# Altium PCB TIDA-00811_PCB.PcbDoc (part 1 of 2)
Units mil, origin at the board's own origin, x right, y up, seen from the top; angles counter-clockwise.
Board outline 2165.35 x 1968.5 mil, 2 copper layers (Top Layer, Bottom Layer), stack 62 mil thick; 184 components, 89 nets, 461 pads, 152 vias.
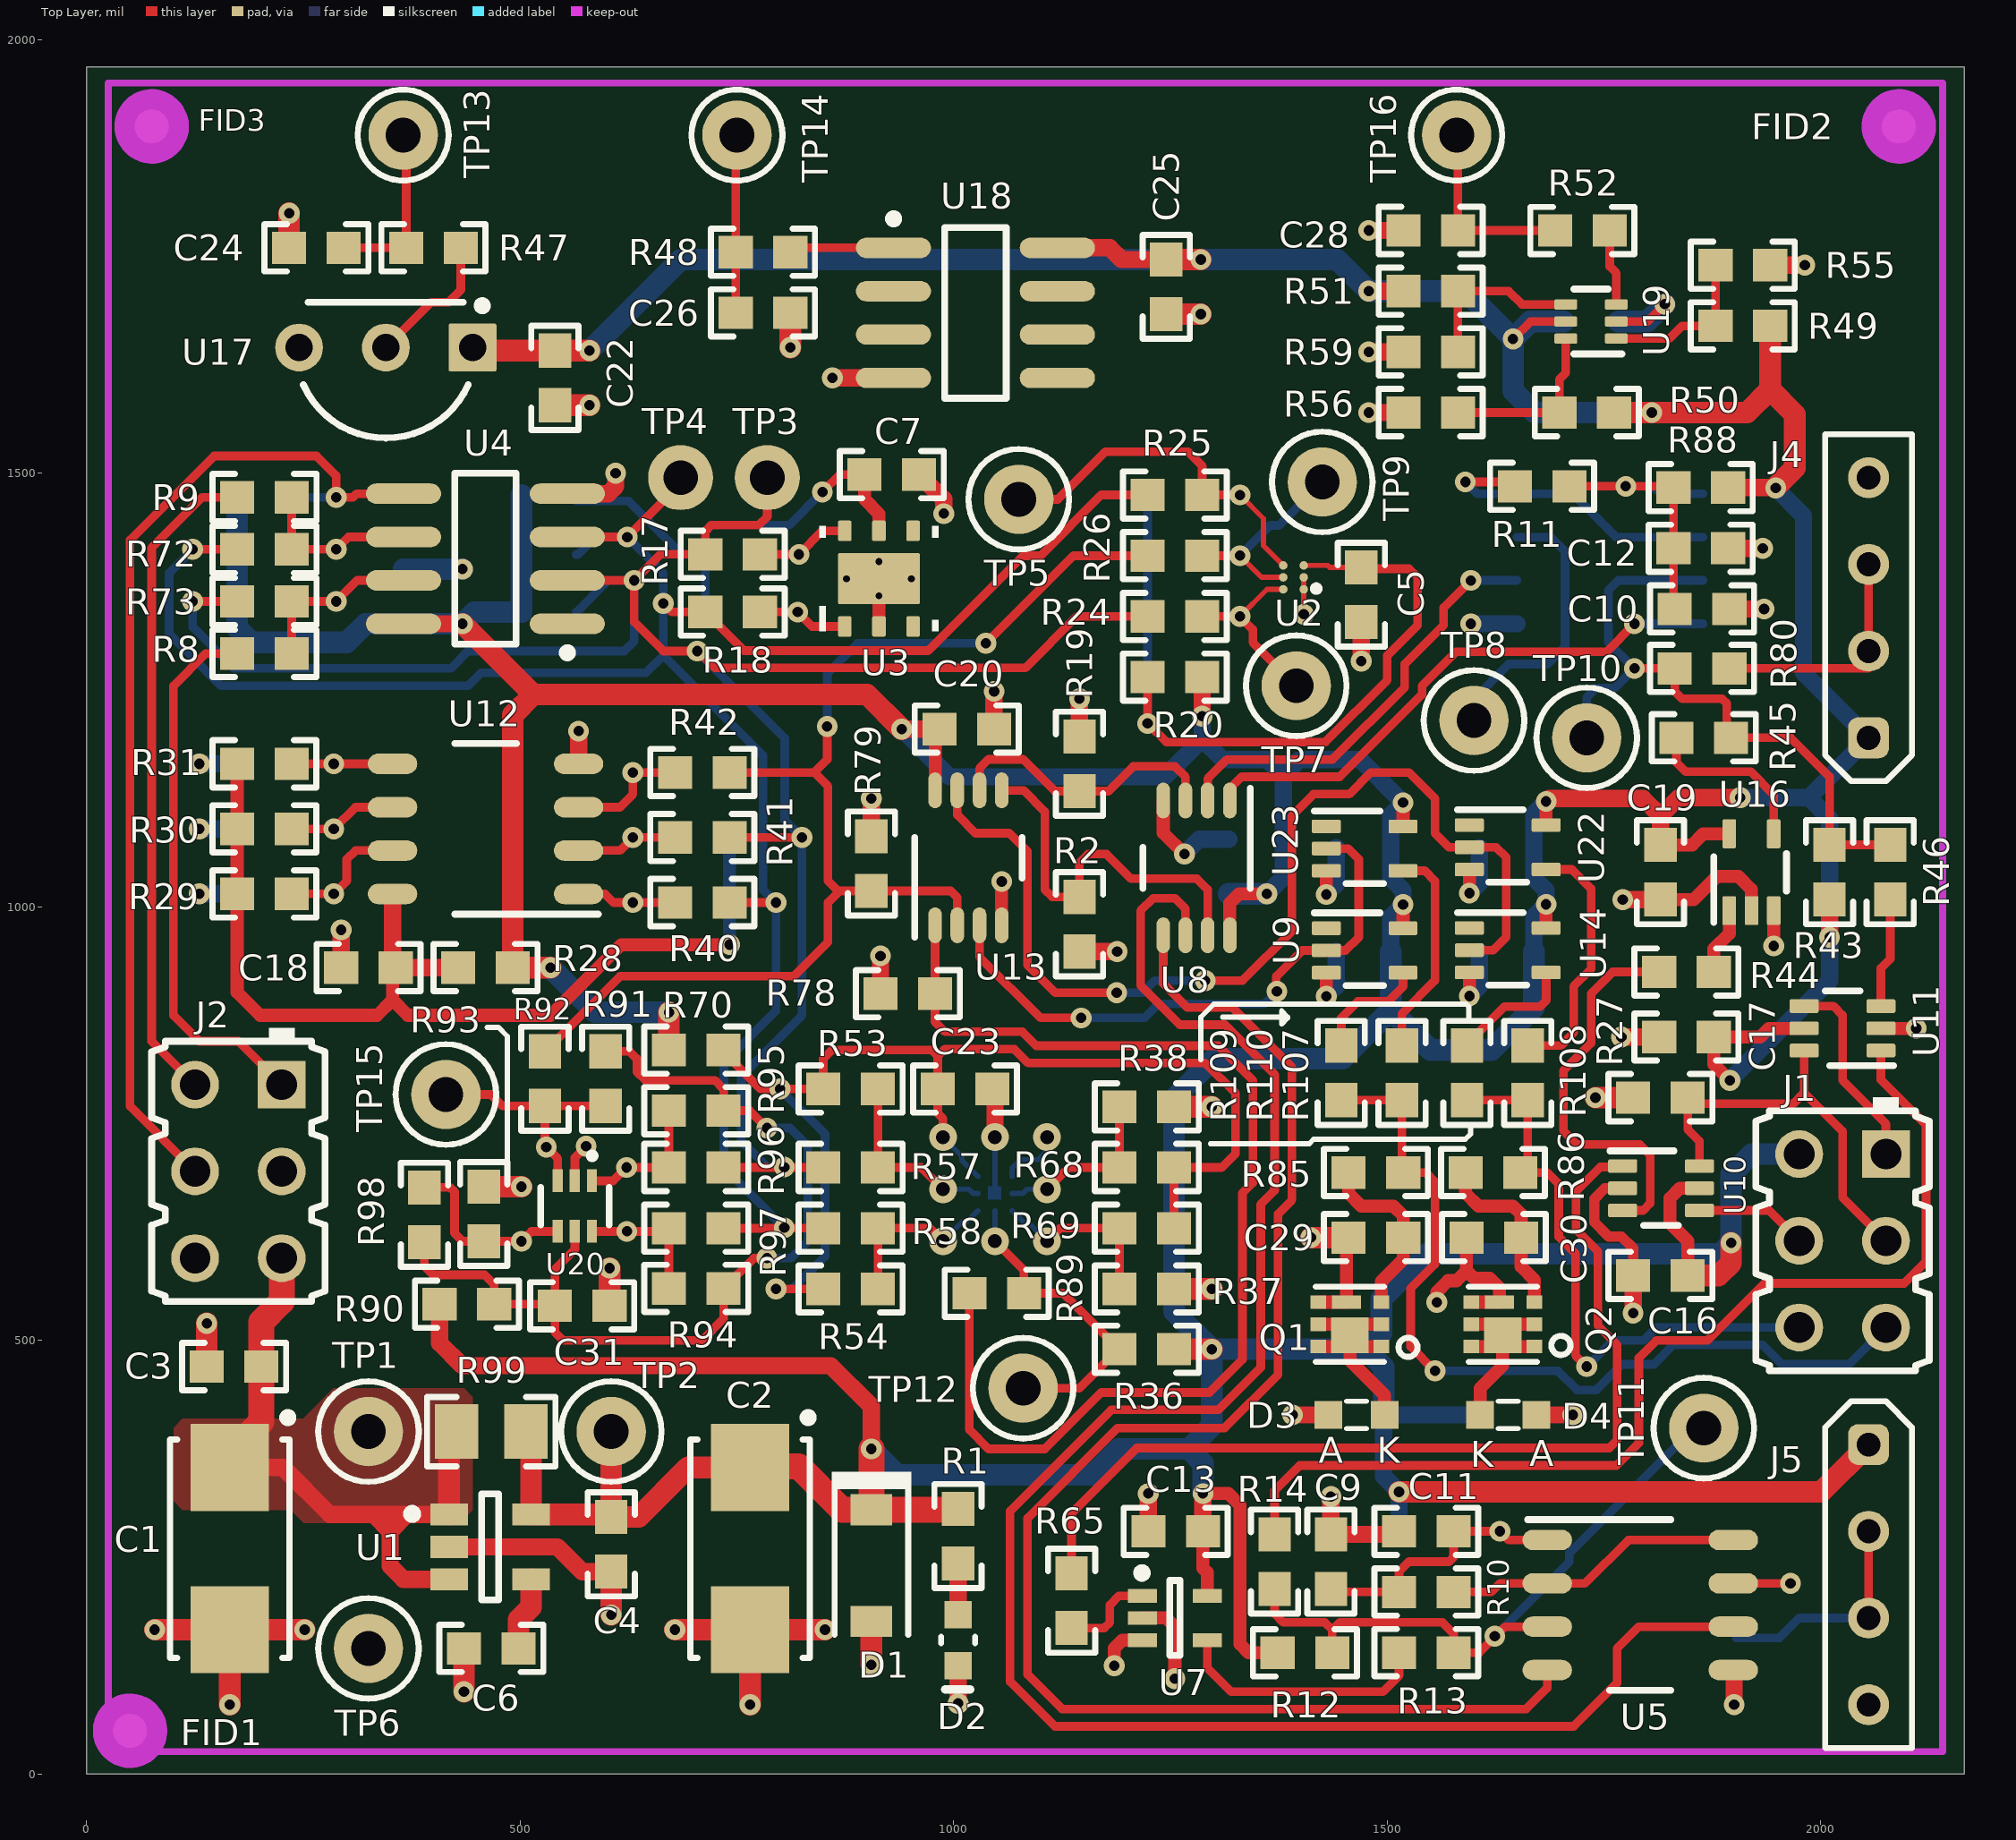
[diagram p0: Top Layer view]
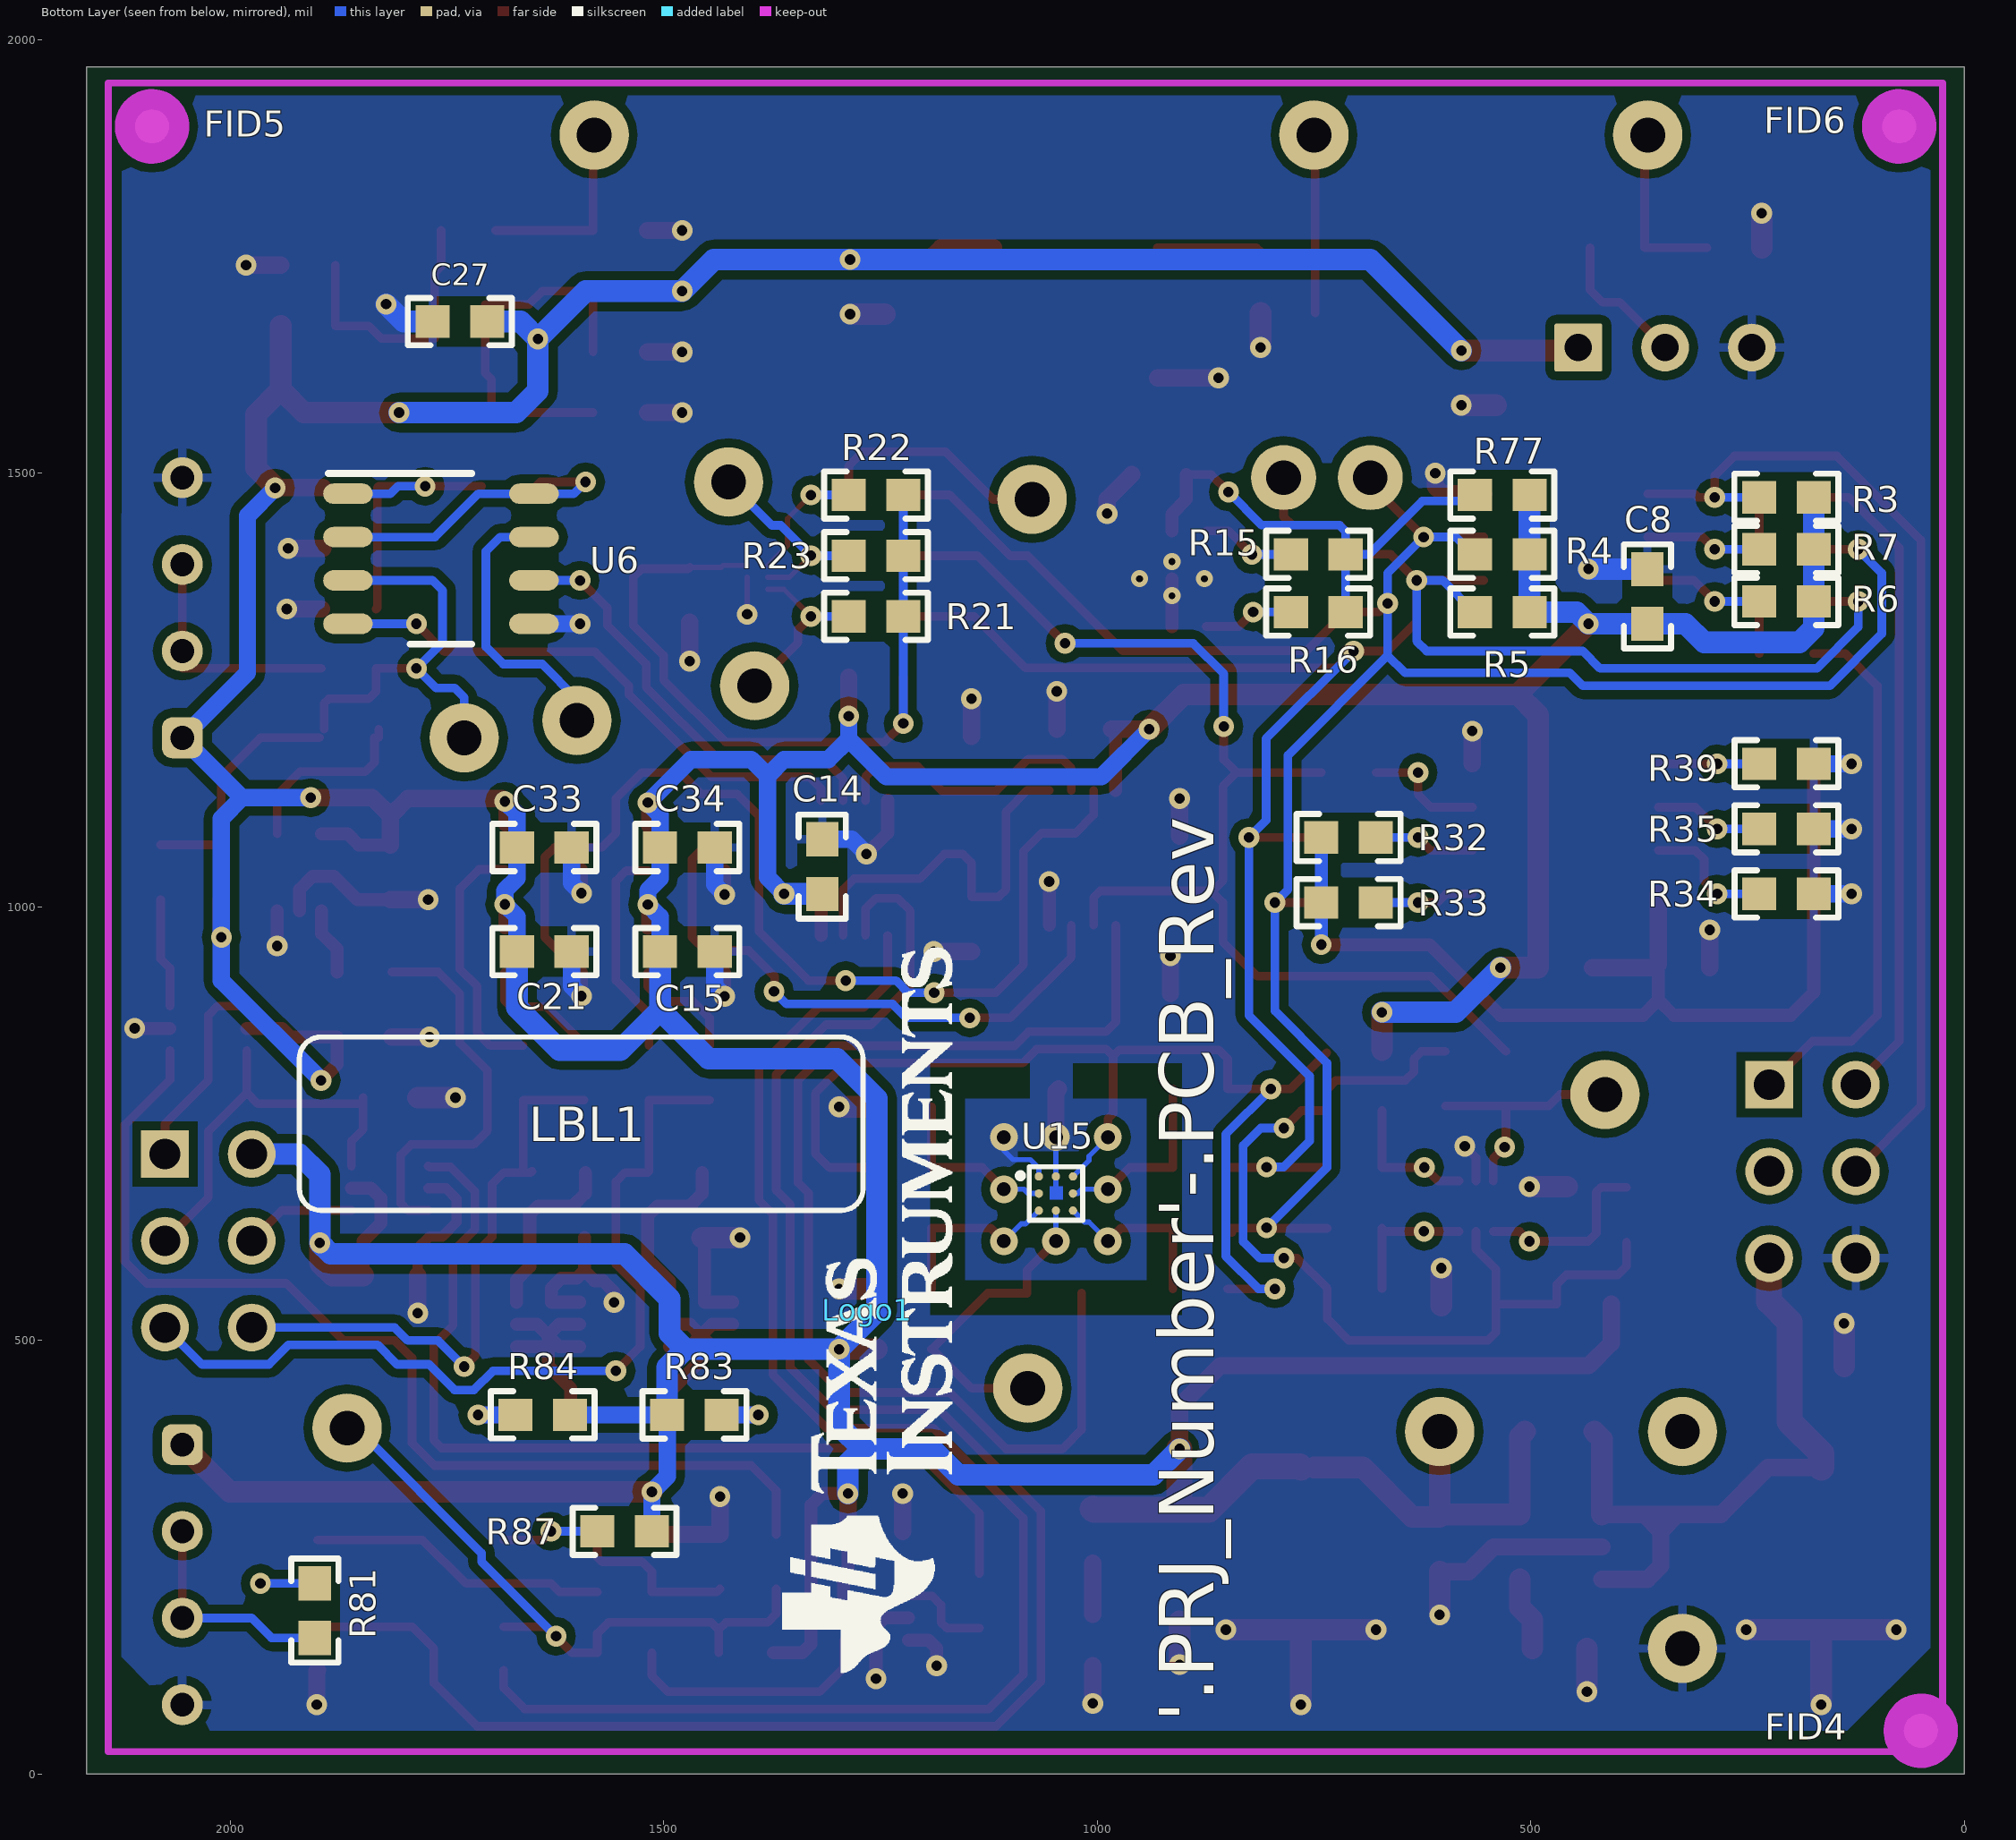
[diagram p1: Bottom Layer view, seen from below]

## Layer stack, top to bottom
Top Solder: solder mask 0.4, Solder Resist, Dk 3.5
Top Layer: signal copper 1.4
Dielectric1: core 59.2, FR-4 High Tg, Dk 4.8
Bottom Layer: signal copper 1.4
Bottom Solder: solder mask 0.4, Solder Resist, Dk 3.5

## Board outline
0,0 0,1968.5 2165.35,1968.5 2165.35,0

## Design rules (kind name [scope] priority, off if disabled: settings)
AcuteAngle [All] p1: minimum=4.50000000000000E+0001 checktracksonly=FALSE
AssemblyTestPointUsage [All] p1: valid=2
Clearance Clearance_1 [All] p1: gap=10 except(7.87: SMDPad-SMDPad)
Clearance Clearance_Trace [inpolygon vs istrack] p2: gap=15 except(7.87: SMDPad-SMDPad)
Clearance Clearance_Poly [InPolygon] p3: gap=25 except(15: Track-Poly Via-Poly)
Clearance [All] p4: gap=7.87
ComponentClearance ComponentClearance_MountingHoles_FiducialMarks [InComponentClass('Mounting Holes') vs InComponentClass('FiducialMark')] p1: gap=50 collisioncheckmode=3 verticalgap=10 showdistances=FALSE
ComponentClearance ComponentClearance_Shunt [InComponentClass('Header') vs InComponentClass('Shunt')] p2: gap=0 collisioncheckmode=3 verticalgap=0 showdistances=FALSE
ComponentClearance ComponentClearance_Logo [InComponentClass('Logo')] p3: gap=50 collisioncheckmode=3 verticalgap=10 showdistances=FALSE
ComponentClearance ComponentClearance_ScrewToNut [(HasFootprint('NY PMS 440 0025 PH')) vs (HasFootprint('Keystone_1902C'))] p4: gap=5 collisioncheckmode=3 verticalgap=10 showdistances=FALSE
ComponentClearance ComponentClearance_MountingHoles [InComponentClass('Mounting Holes')] p5: gap=250 collisioncheckmode=3 verticalgap=100000 showdistances=FALSE
ComponentClearance ComponentClearance_SmallPassives [HasFootprint('0201*') or HasFootprint('0402*') or HasFootprint('0508') or HasFootprint('0603*') or HasFootprint('0612') or HasFootprint('0805*') or HasFootprint('0815*') or HasFootprint('0830*') or HasFootprint('1206*') or HasFootprint('1210*') or HasFootprint('1808*') or HasFootprint('1812*') or HasFootprint('1825*') or HasFootprint('2010*') or HasFootprint('2220*') or HasFootprint('2225*') or HasFootprint('2512*') or HasFootprint('2728*') or HasFootprint('3518*') vs HasFootprint('0201*') or HasFootprint('0402*') or HasFootprint('0508') or HasFootprint('0603*') or HasFootprint('0612') or HasFootprint('0805*') or HasFootprint('0815*') or HasFootprint('0830*') or HasFootprint('1206*') or HasFootprint('1210*') or HasFootprint('1808*') or HasFootprint('1812*') or HasFootprint('1825*') or HasFootprint('2010*') or HasFootprint('2220*') or HasFootprint('2225*') or HasFootprint('2512*') or HasFootprint('2728*') or HasFootprint('3518*')] p6: gap=14.96 collisioncheckmode=3 verticalgap=10 showdistances=FALSE
ComponentClearance ComponentClearance_THtoSMT [IsThruComponent vs IsSMTComponent] p7: gap=40 collisioncheckmode=3 verticalgap=30 showdistances=FALSE
ComponentClearance ComponentClearance_THtoTH [IsThruComponent vs IsThruComponent] p8: gap=30 collisioncheckmode=3 verticalgap=30 showdistances=FALSE
ComponentClearance [All] p9: gap=30 collisioncheckmode=3 verticalgap=10 showdistances=FALSE
DiffPairsRouting [All] p1: maxlimit=100 minlimit=10 mostfreqgap=10 toplayer_minwidth=15 toplayer_maxwidth=15 toplayer_prefwidth=15 bottomlayer_minwidth=15 bottomlayer_maxwidth=15 bottomlayer_prefwidth=15 maxuncoupledlength=1000
FabricationTestPointUsage TestPointUsage [All] p1: valid=2 allowmultiple=FALSE
FabricationTestpoint Testpoint [All] p1: side=3 testpointundercomponent=TRUE minsize=40 maxsize=100 preferedsize=60 minholesize=0 maxholesize=40 preferedholesize=32 testpointgrid=1 allowsidetop=TRUE allowsidebottom=TRUE usegrid=TRUE gridtolerance=0.01
FanoutControl Fanout_LCC [IsLCC] p1: bgadir=Out bgaviamode=Centered fanoutstyle=Auto fanoutdirection=Alternating viagrid=1 // Fanout_LCC (Default Rule)
FanoutControl Fanout_BGA [IsBGA] p2: bgadir=Out bgaviamode=Centered fanoutstyle=Auto fanoutdirection=Alternating viagrid=1 // Fanout_BGA (Default Rule)
FanoutControl Fanout_Default [All] p4: bgadir=Out bgaviamode=Centered fanoutstyle=Auto fanoutdirection=Alternating viagrid=1 // Fanout_Default (Default Rule)
FanoutControl Fanout_Small [(CompPinCount < 5)] p5: bgadir=Out bgaviamode=Centered fanoutstyle=Auto fanoutdirection=OutThenIn viagrid=1 // Fanout_Small (Default Rule)
HoleSize [All] p1: absolutevalues=TRUE maxlimit=251 minlimit=7.87 maxpercent=80.000 minpercent=20.000
MinimumAnnularRing MinimumAnnularRing_ThermalPadVias [IsVia and InAnyComponent] p1: minimumring=5.91
MinimumAnnularRing [All] p2: minimumring=6
MinimumSolderMaskSliver MinimumSolderMaskSliver_Logo [InComponentClass('Logo') vs InComponentClass('Logo')] p1: minsoldermaskwidth=0.7
MinimumSolderMaskSliver [All] p2: minsoldermaskwidth=3
PlaneConnect [All] p1: planeconnectstyle=Relief reliefexpansion=10 reliefentries=4 reliefconductorwidth=10 reliefairgap=10
PolygonConnect PolygonConnect_VIA [All vs isVIA] p1: connectstyle=Direct reliefconductorwidth=10 reliefentries=4 polygonreliefangle="90 Angle" airgapwidth=10
PolygonConnect PolygonConnect_DCIN [InNet('DC_IN') vs InNet('DC_IN')] p2: connectstyle=Direct reliefconductorwidth=10 reliefentries=4 polygonreliefangle="90 Angle" airgapwidth=10
PolygonConnect [All] p3: connectstyle=Relief reliefconductorwidth=10 reliefentries=4 polygonreliefangle="90 Angle" airgapwidth=10
RoutingVias ThermalPadVias [IsVia and InAnyComponent] p1: holewidth=7.87 width=19.68 viastyle="Through Hole" minholewidth=7.87 minwidth=19.68 maxholewidth=12.99 maxwidth=23.62
RoutingVias [All] p2: holewidth=12 width=24 viastyle="Through Hole" minholewidth=12 minwidth=24 maxholewidth=20 maxwidth=40
SilkToSilkClearance SilkToSilkClearance_Pb-FreeLogo [(HasFootprint('Pb-Free_Overlay_Medium') OR HasFootprint('Pb-Free_Overlay_Small')) vs (HasFootprint('Pb-Free_Overlay_Medium') OR HasFootprint('Pb-Free_Overlay_Small'))] p1: silktosilkclearance=0
SilkToSilkClearance [All] p2: silktosilkclearance=0.1
SilkToSolderMaskClearance SilkToComponentPadClearance [IsPad and InAnycomponent] p1: minsilkscreentomaskgap=2 clearancetoexposedcopper=TRUE
SilkToSolderMaskClearance "Silk to Solder Mask Opening" [IsPad] p2: minsilkscreentomaskgap=2 clearancetoexposedcopper=TRUE
SolderMaskExpansion [All] p1: expansion=1.97
Width [All] p1: maxlimit=100 minlimit=6 preferedwidth=10 checkconnectedcopper=TRUE
16 further rules are at their usual default settings.

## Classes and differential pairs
component class TIDA-00811_Pg4: C1 C2 C3 C4 C5 C6 C7 C18 C20 C21 C22 C23 C24 C25 C26 C27 C28 C30 C31 C33 D1 D2 D4 Q2 R1 R15 R16 R17 R18 R20 R21 R22 R23 R24 R25 R26 R28 R29 R30 R31 R32 R33 R34 R35 R36 R37 R38 R39 R40 R41 R42 R47 R48 R49 R50 R51 R52 R53 R54 R55 R56 R57 R58 R59 R68 R69 R70 R77 R78 R79 R84 R86 R89 R90 R91 R92 R93 R94 R95 R96 R97 R98 R99 R107 R108 TP1 TP2 TP5 TP6 TP7 TP9 TP12 TP13 TP14 TP15 TP16 U1 U2 U3 U12 U13 U14 U15 U17 U18 U19 U20 U22
component class TIDA-00811_Pg3: C8 C16 C17 J1 J2 R3 R4 R5 R6 R7 R8 R9 R27 R72 R73 TP3 TP4 U4 U10 U11
component class Header: J1 J2 J4 J5
component class Label: LBL1
component class AssemblyNote: ZZ1 ZZ2 ZZ3 ZZ4
component class FiducialMark: FID1 FID2 FID3 FID4 FID5 FID6
component class TIDA-00811_Pg6_EVM_Hardware: FID1 FID2 FID3 FID4 FID5 FID6 LBL1 Logo1 ZZ1 ZZ2 ZZ3 ZZ4
component class Logo: Logo1
component class TIDA-00811_Pg5: C9 C10 C11 C12 C13 C14 C15 C19 C29 C34 D3 J4 J5 Q1 R2 R10 R11 R12 R13 R14 R19 R43 R44 R45 R46 R65 R80 R81 R83 R85 R87 R88 R109 R110 TP8 TP10 TP11 U5 U6 U7 U8 U9 U16 U23

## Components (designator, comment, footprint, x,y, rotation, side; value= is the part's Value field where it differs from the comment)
C1 "293D106X9025C2TE3" 6032-28 165,260 r270 top
C2 "293D106X9025C2TE3" 6032-28 765,260 r270 top
C3 "06033C104JAT2A" 0603#1 170,470 r0 top
C4 "06033C104JAT2A" 0603#2 605,265 r270 top
C5 "06033C104JAT2A" 0603#2 1470,1360 r90 top
C6 "C1608C0G1E103J080AA" 0603#2 466.66,145 r180 top
C7 "06033C104JAT2A" 0603#2 928.5,1498.5 r180 top
C8 "06033C104JAT2A" 0603#2 365.36,1358 r90 bottom
C9 "06033C104JAT2A" 0603#2 1435,245 r90 top
C10 "06033C104JAT2A" 0603#2 1863.01,1343.54 r0 top
C11 "06033C104JAT2A" 0603#2 1545,280 r0 top
C12 "06033C104JAT2A" 0603#2 1861.51,1413.54 r180 top
C13 "06033C104JAT2A" 0603#2 1255.91,280 r0 top
C14 "06033C104JAT2A" 0603#2 1317,1046.5 r270 bottom
C15 "06033C104JAT2A" 0603#2 1472.59,948.54 r0 bottom
C16 "06033C104JAT2A" 0603#2 1815,575 r180 top
C17 "06033C104JAT2A" 0603#2 1845,850 r180 top
C18 "06033C104JAT2A" 0603#2 325,930 r0 top
C19 "06033C104JAT2A" 0603#2 1815,1040 r90 top
C20 "06033C104JAT2A" 0603#2 1015,1205 r180 top
C21 "06033C104JAT2A" 0603#2 1637.59,948.54 r0 bottom
C22 "06033C104JAT2A" 0603#2 540,1610 r270 top
C23 "06033C104JAT2A" 0603#2 1013.02,790 r180 top
C24 "06033C104JAT2A" 0603#2 265,1760 r0 top
C25 "06033C104JAT2A" 0603#2 1245,1715 r270 top
C26 "06033C104JAT2A" 0603#2 780,1685 r180 top
C27 "06033C104JAT2A" 0603#2 1735,1675 r0 bottom
C28 "06033C104JAT2A" 0603#2 1550,1780 r0 top
C29 "06033C104JAT2A" 0603#2 1486.88,618.66 r180 top
C30 "06033C104JAT2A" 0603#2 1622.9,618.66 r180 top
C31 "06033C104JAT2A" 0603#2 571.54,540 r180 top
C33 "06033C104JAT2A" 0603#2 1637.59,1068.54 r0 bottom
C34 "06033C104JAT2A" 0603#2 1472.59,1068.54 r0 bottom
D1 "MMSZ5227B-7-F" SOD-123 905,240.53 r270 top
D2 "LG L29K-G2J1-24-Z" "LG L29K_GREEN" 1005,154.53 r270 top
D3 "LED_LG L29K-G2J1-24-Z" LED0603AA 1464.42,414.25 r180 top
D4 "LED_LG L29K-G2J1-24-Z" LED0603AA 1639.42,414.25 r0 top
FID1 "Fiducial" Fiducial10-20 50,50 r0 top
FID2 "Fiducial" Fiducial10-20 2090,1900 r0 top
FID3 "Fiducial" Fiducial10-20 75,1900 r0 top
FID4 "Fiducial" Fiducial10-20 50,50 r180 bottom
FID5 "Fiducial" Fiducial10-20 2090,1900 r180 bottom
FID6 "Fiducial" Fiducial10-20 75,1900 r180 bottom
J1 "61300621121" Mill-Max_802-10-006-10-001000 2025,615 r270 top
J2 "61300621121" Mill-Max_802-10-006-10-001000 175,695 r270 top
J4 "61300411121" Mill-Max_342-xx-104-00-592000 2055,1345 r90 top
J5 "61300411121" Mill-Max_342-xx-104-00-592000 2055,230 r270 top
LBL1 "Size: 0.65\" x 0.20 \"" Label_650x200 1595,750 r180 bottom
Logo1 "Texas Instruments" TI_Stacked_Overlay_Small 1265,535 r90 bottom
Q1 "CSD17571Q2" SON_CSD17571Q2 1456.88,518.66 r90 top
Q2 "CSD17571Q2" SON_CSD17571Q2 1633.2,518.66 r90 top
R1 "RC0603FR-071KL" 0603#2 1005,274.53 r90 top
R2 "RC0603JR-070RL" 0603#2 1145,980 r270 top
R3 "RC0603FR-074K7L" 0603#2 205.02,1472.27 r180 bottom
R4 "RC0603FR-074K7L" 0603#2 532.84,1406.5 r180 bottom
R5 "RC0603FR-074K7L" 0603#2 532.84,1340 r180 bottom
R6 "RC0603FR-074K7L" 0603#2 205.02,1352.27 r180 bottom
R7 "RC0603FR-074K7L" 0603#2 205.02,1412.27 r180 bottom
R8 "CRCW060310R0FKEA" 0603#2 205.02,1292.27 r180 top
R9 "CRCW060310R0FKEA" 0603#2 205.02,1472.27 r180 top
R10 "RC0603JR-070RL" 0603#2 1545,210 r0 top
R11 "RC0603JR-070RL" 0603#2 1678.5,1485 r180 top
R12 "RC0603FR-073K3L" 0603#2 1405,140 r180 top
R13 "RC0603FR-07100RL" 0603#2 1545,140 r0 top
R14 "RC0603FR-07100RL" 0603#2 1370,245 r270 top
R15 "RC0603FR-074K7L" 0603#2 745,1406.5 r180 bottom
R16 "RC0603FR-074K7L" 0603#2 745,1340 r180 bottom
R17 "CRCW060310R0FKEA" 0603#2 745,1406.57 r180 top
R18 "CRCW060310R0FKEA" 0603#2 745,1340.07 r180 top
R19 "RC0603JR-070RL" 0603#2 1145,1165 r270 top
R20 "RC0603JR-070RL" 0603#2 1255,1265 r0 top
R21 "RC0603FR-074K7L" 0603#2 1255,1335 r180 bottom
R22 "RC0603FR-074K7L" 0603#2 1255,1475 r180 bottom
R23 "RC0603FR-074K7L" 0603#2 1255,1405 r180 bottom
R24 "CRCW060310R0FKEA" 0603#2 1255,1335 r180 top
R25 "CRCW060310R0FKEA" 0603#2 1255,1475 r180 top
R26 "RC0603JR-070RL" 0603#2 1255,1405 r180 top
R27 "RC0603FR-074K7L" 0603#2 1815,780 r0 top
R28 "RC0603JR-070RL" 0603#2 460,930 r0 top
R29 "RC0603FR-074K7L" 0603#2 205,1015 r180 top
R30 "RC0603FR-074K7L" 0603#2 205,1090 r180 top
R31 "RC0603FR-074K7L" 0603#2 205,1165 r180 top
R32 "RC0603FR-074K7L" 0603#2 710,1080 r0 bottom
R33 "RC0603FR-074K7L" 0603#2 710,1005 r0 bottom
R34 "RC0603JR-070RL" 0603#2 205,1015 r180 bottom
R35 "RC0603JR-070RL" 0603#2 205,1090 r180 bottom
R36 "RC0603JR-072K2L" 0603#2 1222.53,490 r0 top
R37 "RC0603JR-070RL" 0603#2 1222.53,559.5 r180 top
R38 "RC0603JR-070RL" 0603#2 1222.53,769.5 r180 top
R39 "RC0603JR-070RL" 0603#2 205,1165 r180 bottom
R40 "CRCW060310R0FKEA" 0603#2 710,1005 r0 top
R41 "CRCW060310R0FKEA" 0603#2 710,1080 r0 top
R42 "RC0603JR-070RL" 0603#2 710,1155 r0 top
R43 "RC0603FR-073K3L" 0603#2 2010,1040 r270 top
R44 "RC0603JR-070RL" 0603#2 1845,925 r180 top
R45 "RC0603FR-07100RL" 0603#2 1865,1195 r0 top
R46 "RC0603FR-07100RL" 0603#2 2080,1040 r90 top
R47 "CRCW06031K50FKEA" 0603#2 400,1760 r180 top
R48 "CRCW06031K50FKEA" 0603#2 780,1755 r180 top
R49 "RC0603FR-074K7L" 0603#2 1910,1670 r0 top
R50 "RC0603FR-074K7L" 0603#2 1730,1570 r0 top
R51 "RC0603FR-074K7L" 0603#2 1550,1710 r180 top
R52 "CRCW06031K50FKEA" 0603#2 1725,1780 r180 top
R53 "RC0603FR-074K7L" 0603#2 881.03,790 r180 top
R54 "RC0603FR-074K7L" 0603#2 881.03,559.5 r180 top
R55 "RC0603FR-074K7L" 0603#2 1910,1740 r180 top
R56 "RC0603FR-074K7L" 0603#2 1550,1570 r0 top
R57 "CRCW060310R0FKEA" 0603#2 881.03,699.5 r0 top
R58 "CRCW060310R0FKEA" 0603#2 881.03,629.5 r0 top
R59 "RC0603FR-074K7L" 0603#2 1550,1640 r0 top
R65 "RC0603JR-070RL" 0603#2 1135.91,200 r90 top
R68 "RC0603FR-074K7L" 0603#2 1222.53,699.5 r0 top
R69 "RC0603FR-074K7L" 0603#2 1222.53,629.5 r0 top
R70 "RC0603JR-070RL" 0603#2 703.03,835 r180 top
R72 "RC0603JR-070RL" 0603#2 205.02,1412.27 r180 top
R73 "RC0603JR-070RL" 0603#2 205.02,1352.27 r180 top
R77 "RC0603JR-070RL" 0603#2 532.84,1475 r180 bottom
R78 "RC0603FR-074K7L" 0603#2 947.01,900 r180 top
R79 "RC0603FR-074K7L" 0603#2 905,1050 r90 top
R80 "RC0603JR-070RL" 0603#2 1863.01,1275 r180 top
R81 "RC0603JR-070RL" 0603#2 1902.28,188.5 r270 bottom
R83 "CRCW0603300RJNEA" 0603#2 1464.42,414.25 r0 bottom
R84 "CRCW0603300RJNEA" 0603#2 1639.42,414.25 r180 bottom
R85 "CRCW0603300RJNEA" 0603#2 1486.88,693.66 r180 top
R86 "CRCW0603300RJNEA" 0603#2 1621.88,693.66 r180 top
R87 "RC0603JR-070RL" 0603#2 1545,280 r0 bottom
R88 "RC0603JR-070RL" 0603#2 1861.51,1483.54 r180 top
R89 "RC0603JR-070RL" 0603#2 1049.53,554.5 r180 top
R90 "RC0603JR-070RL" 0603#2 438.53,541.94 r180 top
R91 "CRCW060310K0JNEA" 0603#2 598.53,801.94 r90 top
R92 "RC0603JR-070RL" 0603#2 528.53,801.94 r90 top
R93 "RC0603JR-070RL" 0603#2 458.03,645.91 r90 top
R94 "RC0603FR-074K7L" 0603#2 703.03,560 r0 top
R95 "RC0603FR-074K7L" 0603#2 703.03,765 r0 top
R96 "CRCW060310R0FKEA" 0603#2 703.03,699.5 r0 top
R97 "CRCW060310R0FKEA" 0603#2 703.03,629.43 r0 top
R98 "RC0603FR-074K7L" 0603#2 389.53,645 r270 top
R99 "CRCW08050000Z0EA" 0805_HV 466.66,395 r0 top
R107 "RC0603JR-070RL" 0603#2 1591.88,808.66 r270 top
R108 "RC0603JR-070RL" 0603#2 1661.88,808.66 r270 top
R109 "RC0603JR-070RL" 0603#2 1446.88,808.66 r270 top
R110 "RC0603JR-070RL" 0603#2 1516.88,808.66 r270 top
TP1 "5000" Keystone5000 325,395 r0 top
TP2 "5000" Keystone5000 605,395 r0 top
TP3 "TP-5001-BLACK" TH-40 785,1495 r0 top
TP4 "TP-5001-BLACK" TH-40 685,1495 r0 top
TP5 "5000" Keystone5000 1075,1470 r0 top
TP6 "5000" Keystone5000 325,145 r0 top
TP7 "5000" Keystone5000 1395,1255 r0 top
TP8 "5000" Keystone5000 1600,1215 r0 top
TP9 "5000" Keystone5000 1425,1490 r0 top
TP10 "5000" Keystone5000 1730,1195 r0 top
TP11 "5000" Keystone5000 1865,399 r0 top
TP12 "5000" Keystone5000 1080,445 r0 top
TP13 "5000" Keystone5000 365,1890 r90 top
TP14 "5000" Keystone5000 750,1890 r90 top
TP15 "5000" Keystone5000 414.31,783.67 r90 top
TP16 "5000" Keystone5000 1580,1890 r90 top
U1 "LP2985-33DBVR" DBV0005A_N 465.16,262 r0 top
U2 "OPT3006YMF" YMF0006A 1391.81,1380 r180 top
U3 "HDC1080DMBR" DMB0006A 913.69,1378.5 r90 top
U4 "PCA9515ADR" D0008A_N#1 459.85,1401.5 r180 top
U5 "TMP107BIDR" D0008A_N#2 1791.72,195 r0 top
U6 "TMP107BIDR" D0008A_N#2 1756.72,1401.46 r180 bottom
U7 "SN74LVC1G125DCKR" DCK0005A_N#1 1255,180 r0 top
U8 "SN74LVC2G32DCTR" DCT0008A_N 1280,1045 r270 top
U9 "SN74LVC1G14DCKR" DCK0005A_N#2 1473.89,949.84 r0 top
U10 "TS5A3157DCKR" DCK0006A_N 1815.71,675.59 r0 top
U11 "TS5A3157DCKR" DCK0006A_N 2025,860 r180 top
U12 "TMP75BIDR" D0008A_N#2 460,1090 r180 top
U13 "SN74LVC2G32DCTR" DCT0008A_N 1016.89,1056.65 r90 top
U14 "SN74LVC1G14DCKR" DCK0005A_N#2 1638.89,950.04 r0 top
U15 "TMP007AIYZFR" YZF0008AEAE 1047.53,669.5 r180 bottom
U16 "SN74LVC1G125DCKR" DCK0005A_N#2 1920,1040 r90 top
U17 "LMT87LP" LP0003A 345,1645 r90 top
U18 "LM35DM/NOPB" M08A_N 1025,1685 r0 top
U19 "TMP302BDRLR" DRL0006A 1735,1675 r180 top
U20 "TMP102AIDRL" DRL0006A_N 563.03,655 r270 top
U22 "SN74LVC1G17DCKR" DCK0005A_N#2 1638.89,1068.74 r0 top
U23 "SN74LVC1G17DCKR" DCK0005A_N#2 1473.89,1067.24 r0 top
ZZ1 "This Assembly Note is for PCB labels only" AssemblyNoteLabel -48.15,2846 r0 top
ZZ2 "These assemblies are ESD sensitive, ESD precautions shall be observed." AssemblyNote -48.15,2737.11 r0 top
ZZ3 "These assemblies must be clean and free from flux and all contaminants. Use of no clean flux is not acceptable." AssemblyNote -48.15,2648.56 r0 top
ZZ4 "These assemblies must comply with workmanship standards IPC-A-610 Class 2, unless otherwise specified." AssemblyNote -48.15,2560 r0 top

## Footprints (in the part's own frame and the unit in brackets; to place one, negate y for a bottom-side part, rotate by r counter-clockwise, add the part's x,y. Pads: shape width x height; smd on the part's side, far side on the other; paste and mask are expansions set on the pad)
0603#1 [mm] "0603 from SM-752 data"
  rect 1x0.95 smd: 1(0.8,0) 2(-0.8,0)
  silkscreen extent -1.52,-0.69 1.52,0.69, body extent -0.87,-0.47 0.87,0.47, height 1
0603#2 [mm] "0603 from SM-752 data"
  rect 1x0.95 smd: 1(-0.8,0) 2(0.8,0)
  silkscreen extent -1.52,-0.69 1.52,0.69, body extent -0.87,-0.47 0.87,0.47, height 1
0805_HV [mil] "0805 with 30mil clearance between pads"
  rect 50x63 smd: 1(-40,0) 2(40,0)
  silkscreen extent -74,-40 74,40, body extent -43,-29 43,29, height 57
6032-28 [mm] "Medium Density IPC based on Vishay Sprague 293D datasheet."
  rect 2.55x2.3 smd: 1(-2.375,0) 2(2.375,0)
  silkscreen extent -3.96,-1.75 3.2,1.83, body extent -3.15,-1.75 3.15,1.75, height 2.8
AssemblyNote [mil] "Assembly Note"
AssemblyNoteLabel [mil] "Assembly Note for PCB Labels"
D0008A_N#1 [mm] "SOIC, 8-Leads, Body 4.9x3.9mm, Pitch 1.27mm, IPC Medium Density"
  oval 2.2x0.6 smd: 1(-2.4,1.905) 2(-2.4,0.635) 3(-2.4,-0.635) 4(-2.4,-1.905) 5(2.4,-1.905) 6(2.4,-0.635) 7(2.4,0.635) 8(2.4,1.905)
  silkscreen extent -2.53,-2.5 0.9,2.88, body extent -2,-2.5 2,2.5, height 1.75
D0008A_N#2 [mm] "SOIC, 8-Leads, Body 4.9x3.9mm, Pitch 1.27mm, IPC Medium Density"
  oval 1.45x0.6 smd: 1(-2.725,1.905) 2(-2.725,0.635) 3(-2.725,-0.635) 4(-2.725,-1.905) 5(2.725,-1.905) 6(2.725,-0.635) 7(2.725,0.635) 8(2.725,1.905)
  silkscreen extent -3.3,-2.5 0.9,2.5, body extent -3,-2.45 3,2.45, height 1.63
DBV0005A_N [mm] "SOT23, 5-Leads, Body 2.9x1.6mm, Pitch 0.95mm, Lead Span 2.8mm, IPC Medium Density"
  rect 1.1x0.65 smd: 1(-1.2,0.95) 2(-1.2,0) 3(-1.2,-0.95) 4(1.2,-0.95) 5(1.2,0.95)
  silkscreen extent -0.25,-1.55 0.25,1.55, body extent -1.42,-1.46 1.42,1.46, height 1.08
DCK0005A_N#1 [mm] "SOT353, 5-Leads, Body 2x1.3mm, Pitch 0.65mm, Lead Span 2.1mm, IPC Medium Density"
  rect 0.85x0.4 smd: 1(-0.95,0.65) 2(-0.95,0) 3(-0.95,-0.65) 4(0.95,-0.65) 5(0.95,0.65)
  silkscreen extent -0.15,-1.1 0.15,1.1, body extent -1.14,-1 1.14,1, height 0.94
DCK0005A_N#2 [mm] "SOT353, 5-Leads, Body 2x1.3mm, Pitch 0.65mm, Lead Span 2.1mm, IPC Medium Density"
  rrect25% 0.85x0.4 smd: 1(-1.125,0.65) 2(-1.125,0) 3(-1.125,-0.65) 4(1.125,-0.65) 5(1.125,0.65)
  silkscreen extent -1.48,-1.02 0.55,1.1, body extent -1.14,-1 1.14,1, height 0.95
DCK0006A_N [mm] "SOT23, 6-Leads, Body 2x1.3mm, Pitch 0.65mm, Lead Span 2.1mm, IPC Medium Density"
  rrect25% 0.85x0.4 smd: 1(-1.125,0.65) 2(-1.125,0) 3(-1.125,-0.65) 4(1.125,-0.65) 5(1.125,0) 6(1.125,0.65)
  silkscreen extent -1.5,-1.09 0.51,1.09, body extent -1.14,-1 1.14,1, height 0.95
DCT0008A_N [mm] "TSOP, 8-Leads, Body 3x2.8mm, Pitch 0.65mm, IPC Medium Density"
  oval 1.05x0.4 smd: 1(-1.975,0.975) 2(-1.975,0.325) 3(-1.975,-0.325) 4(-1.975,-0.975) 5(1.975,-0.975) 6(1.975,-0.325) 7(1.975,0.325) 8(1.975,0.975)
  silkscreen extent -2.32,-1.57 0.6,1.58, body extent -2.01,-1.47 2.01,1.48, height 1.3
DMB0006A [mm] "TI"
  rrect25% 0.6x0.4 smd: 1(-1.4,1) 2(-1.4,0) 3(-1.4,-1) 4(1.4,-1) 5(1.4,0) 6(1.4,1)
  rrect9% 1.38x1.06 on Top Paste: 7(0,0.63) 7(0,-0.63)
  rrect7% 1.5x2.4 smd paste-0.75: 7(0,0)
  silkscreen extent -1.55,-1.75 1.55,1.75, body extent -1.5,-1.5 1.5,1.5, height 0.81
DRL0006A [mm] "SOTFL, 6-Flat Leads, Body 1.2x1.6x0.6mm, Pitch 0.5mm, TI recommended"
  rrect33% 0.67x0.3 smd: 1(-0.74,0.5) 2(-0.74,0) 3(-0.74,-0.5) 4(0.74,-0.5) 5(0.74,0) 6(0.74,0.5)
  silkscreen extent -0.9,-0.95 0.5,0.95, body extent -0.8,-0.8 0.8,0.8, height 0.61
DRL0006A_N [mm] "SOTFL, 6-Flat Leads, Body 1.2x1.6x0.6mm, Pitch 0.5mm, IPC Medium Density"
  rect 0.67x0.3 smd: 1(-0.74,0.5) 2(-0.74,0) 3(-0.74,-0.5) 4(0.74,-0.5) 5(0.74,0) 6(0.74,0.5)
  silkscreen extent -0.55,-1 0.55,1, body extent -0.65,-0.85 0.65,0.85, height 0.6
Fiducial10-20 [mm]
  round 1 smd mask+0.5: 1(0,0)
  Top Layer keep-out circle w1.178: c0,0 r0.5
Keystone5000 [mil] "For Keystone 500x miniature loop terminals"
  round 80 hole 40: 1(0,0)
  silkscreen extent -58,-58 58,58, body extent -49,-49 49,49, height 182
Label_650x200 [mil] "Thermal Transfer Label"
  silkscreen extent -325,-100 325,100, body extent -325,-100 325,100, height 1
LED0603AA [mil]
  rect 32x32 smd: 1(-32.48,0) 2(32.48,0)
  silkscreen extent -11,-16 11,16
"LG L29K_GREEN" [mm] "OSRAM"
  rect 0.8x0.8 smd: 1(-0.75,0) 2(0.75,0)
  silkscreen extent -0.1,-0.5 1.45,0.5, body extent -0.9,-0.45 0.9,0.45, height 0.67
LP0003A [mm] "TO, Flat Index; 3 In-Line, Formed Axial Leads; Body Dia. 4.8mm; Leads 0.56 x 0.41 mm (max)"
  rrect7% 1.4x1.4 hole 0.8: 1(0,-2.54)
  round 1.4 hole 0.8: 2(0,0) 3(0,2.54)
  silkscreen extent -2.65,-2.95 1.35,2.41, body extent -2.35,-2.83 1.33,2.83, height 9.01
M08A_N [mm] "SOIC, 8-Leads, Body 4.9x3.9mm, Pitch 1.27mm, IPC Medium Density"
  oval 2.2x0.6 smd: 1(-2.4,1.905) 2(-2.4,0.635) 3(-2.4,-0.635) 4(-2.4,-1.905) 5(2.4,-1.905) 6(2.4,-0.635) 7(2.4,0.635) 8(2.4,1.905)
  silkscreen extent -2.52,-2.5 0.9,2.88, body extent -2,-2.5 2,2.5, height 1.75
Mill-Max_342-xx-104-00-592000 [mm] "TH, 5-Leads, Body 400x100mil, Pitch 100mil"
  rrect50% 1.2x1.2 hole 0.7: 1(-3.81,0)
  round 1.2 hole 0.7: 2(-1.27,0) 3(1.27,0) 4(3.81,0)
  silkscreen extent -5.08,-1.27 5.08,1.27, body extent -5.08,-1.27 5.08,1.27, height 11.68
Mill-Max_802-10-006-10-001000 [mm] "Header, 2.54 mm, 3x2, TH"
  rect 1.4x1.4 hole 0.9: 1(-2.54,1.27)
  round 1.4 hole 0.9: 2(-2.54,-1.27) 3(0,1.27) 4(0,-1.27) 5(2.54,1.27) 6(2.54,-1.27)
  silkscreen extent -4.21,-2.54 3.81,2.54, body extent -3.85,-2.54 3.77,2.54, height 8.11
SOD-123 [mm] "On Semi recommended land pattern"
  rect 0.915x1.22 smd: 1(-1.637,0) 2(1.637,0)
  silkscreen extent -2.74,-1.17 2.03,1.17, body extent -1.93,-0.9 1.93,0.9, height 1.35
SON_CSD17571Q2 [mm] "SON, MOSFET, N-CH, 30V, 22A, SON 2X2 MM"
  rect 0.4x0.455 smd mask+0.038: 1(-0.65,-0.923) 2(0,-0.923) 5(0,0.923) 6(-0.65,0.923)
  rect 0.4x0.455 smd: 3(0.65,-0.923) 4(0.65,0.923)
  rect 0.4x0.85 smd mask+0.038: 7(0.65,0.096)
  rect 1.05x1.1 smd mask+0.038: 8(-0.325,0)
  silkscreen extent -1.1,-1.98 1.1,1, body extent -1,-1 1,0.97, height 0.85
TH-40 [mil] "For Keystone 500x miniature loop terminals"
  round 75 hole 40: 1(0,0)
TI_Stacked_Overlay_Small [mil]
  silkscreen extent -418,-98 418,98
YMF0006A [mm] "LGA, 6-Leads, Body 0.856x0.946mm, Pitch 0.35mm"
  round 0.25 smd paste-0.15 mask-0.05: A1(-0.3,0.35) A2(0.3,0.35) B1(-0.3,0) B2(0.3,0) C1(-0.3,-0.35) C2(0.3,-0.35)
  rrect48% 0.21x0.21 on Top Paste: ""(-0.315,0.35) ""(-0.315,0) ""(-0.315,-0.35) ""(0.315,0.35) ""(0.315,0) ""(0.315,-0.35)
  body extent -0.43,-0.47 0.43,0.47, height 0.23
YZF0008AEAE [mm] "WCSP"
  round 0.245 smd paste-0.125: A1(-0.5,0.5) A2(0,0.5) A3(0.5,0.5) B1(-0.5,0) B3(0.5,0) C1(-0.5,-0.5) C2(0,-0.5) C3(0.5,-0.5)
  body extent -0.78,-0.78 0.78,0.78, height 0.63

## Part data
C1 C2: "CAP, TA, 10 µF, 25 V, +/- 10%, 1.5 ohm, SMD"
C3 C4 C5 C7 C8 C9 C10 C11 C12 C13 C14 C15 C16 C17 C18 C19 C20 C21 C23 C31 C33 C34: "CAP, CERM, 0.1 µF, 25 V, +/- 5%, X7R, 0603"
C6: library part C1608C0G1E103J, "CAP, CERM, 0.01 µF, 25 V, +/- 5%, C0G/NP0, 0603"
C22 C24 C25 C26 C27 C28 C29 C30: "CAP, CERM, 0.1uF, 25V, +/-5%, X7R, 0603"
D1: "Diode, Zener, 3.6 V, 500 mW, SOD-123"
D2: "LED, Green, SMD"
D3 D4: "LED SmartLED Green 570NM"
FID1 FID2 FID3 FID4 FID5 FID6: "Fiducial mark.  There is nothing to buy or mount."
J1 J2: library part 802-10-006-10-001000, "Header, 2.54 mm, 3x2, Gold, TH"
J4 J5: library part 342-10-104-00-592000, "Header, 2.54mm, 4x1, Gold, TH"
LBL1: library part THT-14-423-10, "Thermal Transfer Printable Labels, 0.650\" W x 0.200\" H - 10,000 per roll"
Logo1: library part TI_Logo, "Texas Instrument Corporate Signature"
Q1 Q2: "MOSFET, N-CH, 30V, 22A, SON 2X2 MM"
R1: "RES, 1.00 k, 1%, 0.1 W, 0603"
R2 R10 R11 R19 R20 R26 R28 R34 R35 R37 R38 R39 R42 R44 R65 R70 R72 R73 R77 R80 R81 R87 R88 R89 R90 R92 R93 R107 R108 R109 R110: "RES, 0, 5%, 0.1 W, 0603"
R3 R4 R5 R6 R7 R15 R16 R21 R22 R23 R27 R29 R30 R31 R32 R33 R49 R50 R51 R53 R54 R55 R56 R59 R68 R69 R78 R79 R94 R95 R98: "RES, 4.70 k, 1%, 0.1 W, 0603"
R8 R9 R17 R18 R24 R25 R40 R41 R57 R58 R96 R97: "RES, 10.0, 1%, 0.1 W, 0603"
R12 R43: "RES, 3.30 k, 1%, 0.1 W, 0603"
R13 R14 R45 R46: "RES, 100, 1%, 0.1 W, 0603"
R36: "RES, 2.2 k, 5%, 0.1 W, 0603"
R47 R48 R52: "RES, 1.50 k, 1%, 0.1 W, 0603"
R83 R84 R85 R86: "RES, 300 ohm, 5%, 0.1W, 0603"
R91: "RES, 10 k, 5%, 0.1 W, 0603"
R99: "RES, 0, 5%, 0.125 W, 0805"
TP1 TP2 TP5 TP6 TP7 TP8 TP9 TP10 TP11 TP12 TP13 TP14 TP15 TP16: "Test Point, Miniature, Red, TH"
TP3 TP4: "Test Point,  Black, Thru Hole Color Keyed"
U1: "100-mA ULTRA-LOW DROPOUT REGULATOR WITH SHUTDOWN, DBV0005A"
U2: "Ambient Light Sensor, YMF0006A (PICOSTAR-6)"
U3: "Low Power, High Accuracy Digital Humidity Sensor with Temperature Sensor, DMB0006A"
U4: "Dual Bidirectional I2C Bus and SMBus Repeater, 2 Channel Width, 2.3 to 3.6 V, -40 to 85 degC, 8-pin SOIC (D), Green (RoHS & no Sb/Br)"
U5 U6: "TMP107B, D0008A"
U7 U16: "Single Bus Buffer Gate With 3-State Output, DCK0005A"
U8 U13: "Dual 2-Input Positive-OR Gate, DCT0008A"
U9 U14: "SINGLE SCHMITT-TRIGGER INVERTER, DCK0005A"
U10 U11: "10-OHM SPDT ANALOG SWITCH, DCK0006A (SOT-SC70-6)"
U12: "1.4V-Capable Temperature Sensor with I2C/SMBus Interface in LM75 Form Factor & Pinout, D0008A (SOIC-8)"
U15: "Infrared Thermopile Sensor with Integrated Math Engine, YZF0008AEAE"
U17: "IC, TEMP SENSOR PREC ANLG, TO-92, TH"
U18: "Precision Centigrade Temperature Sensor, 8-pin Narrow SOIC, Pb-Free"
U19: "Pin-Selectable Trip Point 1.4V-Capable Family of Temperature Switches, DRL0006A (SOT-OTHER-6)"
U20: "Low Power Digital Temperature Sensor With SMBus/Two-Wire Serial Interface in SOT563, DRL0006A"
U22 U23: "SINGLE SCHMITT-TRIGGER BUFFER, DCK0005A (SOT-5)"
ZZ1: library part AssemblyNoteLabel
ZZ2 ZZ3 ZZ4: library part AssemblyNote

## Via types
v1: diameter 24, hole 12, Top Layer to Bottom Layer, tented both sides, 140 vias
v2: diameter 32, hole 16, Top Layer to Bottom Layer, tented both sides, 8 vias
v3: diameter 19.68, hole 7.87, Top Layer to Bottom Layer, 4 vias

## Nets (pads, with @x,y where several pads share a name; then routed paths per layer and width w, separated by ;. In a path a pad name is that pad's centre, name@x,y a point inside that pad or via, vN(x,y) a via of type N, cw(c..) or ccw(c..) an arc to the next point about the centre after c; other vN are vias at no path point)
+3.3V: C2.1 C4.1 C8.1 C13.2 C14.2 C15.2 C16.1 C17.1 C19.2 C20.2 C21.2 C22.1 C25.1 C27.1 C33.2 C34.2 D1.1 J1.2 J4.1 J5.1 R1.2 R3.2 R4.2 R5.2 R6.2 R7.2 R12.2 R20.2 R28.2 R36.2 R43.2 R49.2 R50.2 R51.2 R70.2 R77.2 R83.2 R84.2 R87.1 R88.1 R90.2 R99.2 TP2.1 U1.5 U4.8 U7.5 U8.8 U9.5 U10.5 U11.5 U13.8 U14.5 U16.5 U17.1 U18.8 U19.5 U22.5 U23.5 | length 12520.1
  Top Layer w10: v1(1645,1655) 1665,1675 U19.5@1705.87,1675
  Top Layer w15: U13.8@978.5,1134.41 978.5,1200 C20.2@983.5,1205 ; C13.2@1287.4,280 1287.4,237.6 1292.4,232.6 U7.5@1292.4,205.59 ; v1(1287.4,323.5) 1316.5,323.5 1330,310 1330,150 1340,140 R12.2@1373.5,140 ; U8.8@1318.39,967.24 1318.39,1004.39 1328.99,1014.99 v1(1360.99,1014.99) ; U9.5@1518.18,975.43 v1(1518.18,1002.76) ; U23.5@1518.18,1092.83 v1(1518.18,1120.16) ; U14.5@1683.18,975.63 v1(1683.18,1002.95) ; U22.5@1683.18,1094.33 v1(1683.18,1121.65) ; C19.2@1815,1071.5 1851.5,1071.5 1864.29,1084.29 U16.5@1894.41,1084.29 ; C16.1@1846.5,575 1846.5,614.5 1825.77,635.23 1825.77,663.97 1837.39,675.59 U10.5@1860,675.59 ; v1(1895,800) 1876.5,818.5 C17.1@1876.5,850 1930,850 1940,860 U11.5@1980.71,860
  Top Layer w20: U4.8@365.36,1326.5 v1(433.5,1326.5) ; R90.2@407.03,541.94 407.03,496.97 433,471 858,471 905,424 v1(905,375) ; v1(940,1205) C20.2@983.5,1205 ; U18.8@1119.49,1760 1180,1760 1193.5,1746.5 C25.1@1245,1746.5 ; v1(1286.5,1220) R20.2@1286.5,1265 ; C13.2@1287.4,280 v1(1287.4,323.5) ; v1(1478.5,1710) R51.2@1518.5,1710 ; v1(1683.18,1121.65) 1686.53,1125 1795,1125 1815,1105 ; C19.2@1815,1071.5 1815,1105 ; R88.1@1893.01,1483.54 v1@1947.46,1483.54 ; v1(1907,1126) 1836,1126 1815,1105 ; v1(2010,965) R43.2@2010,1008.5
  Top Layer w25: v1(433.5,1326.5) 515,1245 ; U17.1@445,1645 448.5,1641.5 C22.1@540,1641.5 v1(580,1641.5) ; R99.2@506.66,395 512.4,389.26 U1.5@512.4,299.4 602.09,299.4 C4.1@605,296.5 ; v1(535,930) R28.2@491.5,930 491.5,1221.5 515,1245 ; TP2.1@605,395 C4.1@605,296.5 ; R70.2@671.54,835 v1(671.54,878.5) ; C2.1@750,353.5 693.5,353.5 636.5,296.5 C4.1@605,296.5 ; v1(940,1205) 900,1245 515,1245 ; C25.1@1245,1746.5 v1(1285,1746.5) ; R36.2@1254.03,490 v1(1297.53,490) ; v1(1513.5,325.49) 2000.49,325.49 J5.1@2055,380 ; R50.2@1761.5,1570 v1(1805,1570) 1915,1570 1941.5,1596.5 ; C16.1@1846.5,575 1882,575 1896.5,589.5 v1(1896.5,612.5) ; R49.2@1941.5,1670 1941.5,1596.5 ; v1@1947.46,1483.54 1970,1506.09 1970,1567.99 1941.5,1596.5
  Top Layer w30: C2.1@765,353.5 766.5,355 821,355 871,305 D1.1@905,305 ; v1(905,375) D1.1@905,305 ; R1.2@1005,306.02 1003.98,305 D1.1@905,305
  Bottom Layer w20: v1(940,1205) 995,1150 1242.99,1150 1286.5,1193.5 ; v1(1286.5,1220) 1286.5,1193.5 ; v1(1360.99,1014.99) 1380,1034 1380,1151 ; C15.2@1504.09,948.54 1504.09,988.66 v1(1518.18,1002.76) 1518.18,1018.82 1504.09,1032.91 C34.2@1504.09,1068.54 1504.09,1106.06 v1(1518.18,1120.16) 1468.34,1170 1399,1170 1380,1151 ; R87.1@1513.5,280 1513.5,325.5 1495.91,343.09 R83.2@1495.91,414.25 R84.2@1607.92,414.25 ; C21.2@1669.09,948.54 1669.09,988.86 v1(1683.18,1002.95) 1683.18,1018.82 1669.09,1032.91 C33.2@1669.09,1068.54 1669.09,1107.56 v1(1683.18,1121.65) ; v1(1895,800) 2010,915 v1(2010,965) 2010,1102 1986,1126 ; v1(1907,1126) 1986,1126 ; v1(1948,1483) 1980,1451 1980,1270 J4.1@2055,1195 1986,1126 ; 1286.5,1193.5 1310,1170 1361,1170 1380,1151
  Bottom Layer w25: R3.2@173.52,1472.27 R7.2@173.52,1412.27 R6.2@173.52,1352.27 173.52,1321.48 190,1305 300,1305 321.5,1326.5 C8.1@365.36,1326.5 v1(433.5,1326.5) 446.99,1340 R5.2@501.35,1340 R4.2@501.35,1406.5 R77.2@501.35,1475 ; v1(535,930) 586.5,878.5 v1(671.54,878.5) ; v1(580,1641.5) 685,1746.5 v1(1285,1746.5) 1442.01,1746.5 v1(1478.5,1710) 1590,1710 v1(1645,1655) ; v1(905,375) 935,345 1160,345 1190,375 1271,375 ; v1(1287.4,323.5) 1287.4,358.6 1271,375 ; C14.2@1317,1015 v1(1360.99,1014.99) ; R83.2@1495.91,414.25 1495.91,469.09 1475,490 ; C15.2@1504.09,948.54 1504.09,880.91 ; C21.2@1669.09,948.54 1669.09,884.09 1620,835 1550,835 1504.09,880.91 ; C27.1@1703.5,1675 1665,1675 v1(1645,1655) ; v1(1805,1570) 1670.02,1570 1645,1595.02 v1(1645,1655) ; J1.2@1975,715 1920,715 1896.5,691.5 v1(1896.5,612.5) 1884,600 1545,600 1493.2,548.2 1493.2,508.2 1475,490 ; 1271,375 1297.53,401.53 v1(1297.53,490) ; v1(1297.53,490) 1254.03,533.5 1254.03,779.03 1300,825 1448.17,825 1504.09,880.91 ; v1(1297.53,490) 1475,490
ALERT_1: U5.4 U8.5 | length 1789.2
  Top Layer w10: U8.5@1241.61,967.24 1241.61,911.67 1269.14,884.14 1320.86,884.14 1390,815 1390,662 1374,646 1374,460.72 1312.28,399 1189,399 1085,295 1085,115 1125,75 1660,75 1684.43,99.43 U5.4@1684.43,120
ALERT_2: U5.6 U8.6 | length 2201.4
  Top Layer w10: U8.6@1267.2,967.24 1267.2,997.8 1255,1010 1230,1010 1215.5,995.5 1215.5,909.5 1260.86,864.14 1312.57,864.14 1370,806.72 1370,673 1354,657 1354,469 1305,420 1181.72,420 1065,303.28 1065,106.72 1116.72,55 1715,55 1765,105 1765,145 1790,170 U5.6@1899,170
ALERT_3: U6.4 U8.1 | length 643.8
  Top Layer w10: U8.1@1318.39,1122.76 1318.39,1136.39 1332,1150 1445,1150 1540,1245 1540,1255 1579.15,1294.15 1752.69,1294.15 v1(1785,1326.46)
  Bottom Layer w10: v1(1785,1326.46) U6.4@1864,1326.46
ALERT_4: U6.6 U8.2 | length 503.8
  Top Layer w10: U8.2@1292.8,1122.76 1292.8,1147.8 1315,1170 1436.72,1170 1520,1253.28 1520,1280 1565,1325 1565,1345 v1(1596.46,1376.46)
  Bottom Layer w10: v1(1596.46,1376.46) U6.6@1649.43,1376.46
DC_IN: C1.1 C3.1 J2.5 R99.1 TP1.1 U1.1 U1.3 | length 812.2
  Top Layer w20: C1.1@165,353.5 226.5,353.5 280.6,299.4 330.6,299.4 ; 369.4,299.4 350,280 ; U1.3@417.91,224.6 365.4,224.6 350,240 350,280 ; U1.1@417.91,299.4 330.6,299.4 ; 330.6,299.4 350,280
  Top Layer w25: TP1.1@310.16,402 TP1.1@311.66,400.5 ; U1.1@417.91,299.4 417.91,386.25 R99.1@426.66,395
  Top Layer w30: C1.1@165,353.5 165,370 201.5,406.5 C3.1@201.5,470 201.5,521.5 225,545 J2.5@225,595
GND: C1.2 C2.2 C3.2 C4.2 C5.1 C6.2 C7.1 C8.2 C9.2 C10.2 C11.1 C12.1 C13.1 C14.1 C15.1 C16.2 C17.2 C18.1 C19.1 C20.1 C21.1 C22.2 C23.1 C24.1 C25.2 C26.1 C27.2 C28.1 C29.2 C30.2 C31.1 C33.1 C34.1 D1.2 D2.2 J2.6 J4.4 J5.4 Q1.4 Q1.7 Q2.4 Q2.7 R2.2 R19.1 R27.1 R34.2 R35.2 R37.1 R38.1 R39.2 R55.1 R56.1 R59.1 R78.2 R79.2 R93.2 TP6.1 U1.2 U2.A1 U2.B1 U3.2 U3.7@913.69,1378.5 U4.4 U5.5 U6.5 U7.2 U7.3 U8.4 U9.3 U10.2 U11.2 U12.4 U13.4 U14.3 U15.A1 U15.A2 U16.2 U16.3 U17.3 U18.4 U19.2 U20.2 U22.3 U23.3 | length 4575.4
  Top Layer w6: v1(1403.62,1337.38) U2.A1@1403.62,1366.22 U2.B1@1403.62,1380
  Top Layer w10: U20.2@563.03,684.13 563.03,711 v1(576.03,724) ; U19.2@1764.13,1675 1800,1675 v1(1820,1695)
  Top Layer w12: U10.2@1771.42,675.59 1750.93,675.59 1738.69,663.35 1738.69,636.65 1755.34,620 1770,620 1783.5,606.5 C16.2@1783.5,575
  Top Layer w15: U3.2@913.69,1323.38 v3(913.69,1358.81) U3.7@913.69,1378.5 ; U13.4@1055.28,978.9 v1(1055.28,1029.28) ; v1(1185,125) 1185,145 1194.41,154.41 U7.3@1217.6,154.41 ; U7.2@1217.6,180 1245,180 1255,170 v1(1255,110) ; U8.4@1241.61,1122.76 1241.61,1085.37 v1(1265.99,1060.99) ; Q1.4@1420.56,544.25 Q1.7@1453.1,544.25 1453.1,616.38 C29.2@1455.38,618.66 ; v1(1429.6,896.93) U9.3@1429.6,924.25 ; v1(1429.6,1014.33) U23.3@1429.6,1041.65 ; C11.1@1510,276.5 C11.1@1513.5,280 ; v1(1557,544) 1557,556 1570,569 1579.81,569 1591.41,580.59 ; C30.2@1591.41,618.66 1591.41,580.59 ; v1(1594.6,897.13) U14.3@1594.6,924.45 ; v1(1594.6,1015.83) U22.3@1594.6,1043.15 ; Q2.4@1596.88,544.25 Q2.7@1629.42,544.25 1629.42,560.58 1618,572 1600,572 1591.41,580.59 ; C19.1@1815,1008.5 1853.5,1008.5 1880,1035 1905,1035 1920,1020 U16.2@1920,995.71 ; v1(1945.59,955) U16.3@1945.59,995.71 ; U11.2@2069.29,860 v1(2110,860)
  Top Layer w20: C18.1@293.5,930 v1(293.5,973.5) ; U1.2@417.91,262 543,262 571.5,233.5 C4.2@605,233.5 ; U4.4@554.34,1476.5 601.5,1476.5 610,1485 v1(610,1500) ; U12.4@567.28,1165 v1(567.28,1202.72) ; v1(860,1610) U18.4@930.51,1610 ; R79.2@905,1081.5 v1(905,1125) ; R78.2@915.51,900 v1(915.51,943.5) ; C7.1@959.99,1498.5 988.5,1469.99 v1(988.5,1453.5) ; v1(1005,81.5) D2.2@1005,125 ; C23.1@1044.52,790 1047.53,786.99 v2(1047.53,734.5) ; C20.1@1046.5,1205 v1(1046.5,1248.5) ; R2.2@1145,948.5 v1(1188.5,948.5) ; R19.1@1145,1196.5 v1(1145,1240) ; C13.1@1224.41,280 v1(1224.41,323.5) ; v1(1435,320) C9.2@1435,276.5 C11.1@1510,276.5 ; v1(1470,1283.5) C5.1@1470,1328.5 ; v1(1478.5,1570) R56.1@1518.5,1570 ; v1(1478.5,1640) R59.1@1518.5,1640 ; v1(1478.5,1780) C28.1@1518.5,1780 ; v1(1770,850) C17.2@1813.5,850 ; v1(1771.5,1008.5) C19.1@1815,1008.5 ; v1(1783.5,531.5) C16.2@1783.5,575 ; C12.1@1893.01,1413.54 v1(1933.01,1413.54) ; C10.2@1894.5,1343.54 v1(1934.5,1343.54) ; U5.5@1899,120 1900,119 v1(1900,80) ; R55.1@1941.5,1740 v1(1981.5,1740)
  Top Layer w25: v1(78.5,166.5) C1.2@165,166.5 ; C3.2@138.5,470 v1(138.5,519.83) ; v1(165,80) C1.2@165,166.5 ; C24.1@233.5,1760 v1(233.5,1800) ; v1(251.5,166.5) C1.2@165,166.5 ; v1(435.17,95.17) C6.2@435.17,145 ; R93.2@458.03,677.4 v1(501.54,677.4) ; C22.2@540,1578.5 v1(580,1578.5) ; C31.1@603.03,540 v1(603.03,583.5) ; v1(605,183.67) C4.2@605,233.5 ; v1(678.5,166.5) C2.2@765,166.5 ; v1(765,80) C2.2@765,166.5 ; v1(811.5,1645) C26.1@811.5,1685 ; v1(851.5,166.5) C2.2@765,166.5 ; v1(905,126.23) D1.2@905,176.06 ; C25.2@1245,1683.5 v1(1285,1683.5) ; R37.1@1254.03,559.5 v1(1297.53,559.5) ; R38.1@1254.03,769.5 v1(1297.53,769.5) ; v1(1411.88,618.66) C29.2@1455.38,618.66 ; v1(1740,780) R27.1@1783.5,780
  Bottom Layer w6: 1047.53,670.5 U15.A2@1047.53,689.18 v2(1047.53,734.5) ; U15.A1@1067.22,689.18 1067.22,698.72 1077.02,708.53 1097.02,708.53 1107.53,719.04 v2(1107.53,734.5)
  Bottom Layer w20: v1(130,1015) R34.2@173.5,1015 ; v1(130,1090) R35.2@173.5,1090 ; v1(130,1165) R39.2@173.5,1165 ; v1(1265.99,1060.99) 1282.99,1077.99 C14.1@1317,1077.99 ; v1(1429.6,896.93) 1441.09,908.43 C15.1@1441.09,948.54 ; v1(1429.6,1014.33) 1441.09,1025.83 C34.1@1441.09,1068.54 ; v1(1594.6,897.13) 1606.09,908.62 C21.1@1606.09,948.54 ; v1(1594.6,1015.83) 1606.09,1027.32 C33.1@1606.09,1068.54 ; v1(1596.46,1326.46) U6.5@1649.43,1326.46
  Bottom Layer w25: C8.2@365.36,1389.5 v1(433.5,1389.5) ; C27.2@1766.5,1675 1800,1675 v1(1820,1695)
  other v3: 876.29,1378.5 951.09,1378.5 913.69,1398.18
I2C_SCL: R5.1 R17.2 R24.2 R41.2 R57.1 R73.2 R96.2 TP3.1 U4.2 | length 2688.6
  Top Layer w10: v1(122.27,1352.27) R73.2@173.52,1352.27 ; U4.2@554.34,1376.5 v1(631.5,1376.5) ; R96.2@734.53,699.5 804.03,699.5 v1(804.53,700) 805.03,699.5 R57.1@849.54,699.5 ; R41.2@741.5,1080 v1(825,1080) ; TP3.1@785,1495 785,1450 775.27,1440.27 720.27,1440.27 713.5,1433.5 R17.2@713.5,1406.57 661.57,1406.57 v1(631.5,1376.5) ; R24.2@1223.5,1335 1142,1335 1082.5,1275.5 724.5,1275.5 705,1295 v1(704.14,1295) 665,1295 631.5,1328.5 v1(631.5,1376.5)
  Bottom Layer w10: v1(122.27,1352.27) 122.27,1322.73 170,1275 420,1275 440,1295 620,1295 631.5,1306.5 v1(631.5,1376.5) 601.5,1376.5 565,1340 R5.1@564.34,1340 ; v1(704.14,1295) 805,1194.14 805,1100 v1(825,1080) 825,875 755,805 755,730 785,700 v1(804.53,700)
I2C_SDA: R4.1 R18.2 R25.2 R40.2 R58.1 R72.2 R97.2 TP4.1 U4.3 | length 2752.1
  Top Layer w10: v1(122.27,1412.27) R72.2@173.52,1412.27 ; U4.3@554.34,1426.5 v1(623.5,1426.5) 685,1488.01 TP4.1@685,1495 ; v1(665,1350) 674.93,1340.07 R18.2@713.5,1340.07 758.07,1295.5 970.5,1295.5 1080,1405 1100,1405 1170,1475 R25.2@1223.5,1475 ; R97.2@734.53,629.43 804.96,629.43 805.03,629.5 R58.1@849.54,629.5 R58.1@844.47,624.43 ; R40.2@741.5,1005 v1(795,1005)
  Bottom Layer w10: v1(122.27,1412.27) 95,1385 95,1315 155,1255 440,1255 455,1270 645,1270 665,1290 ; R4.1@564.34,1406.5 566.5,1406.5 586.5,1426.5 v1(623.5,1426.5) 665,1385 v1(665,1350) 665,1290 ; v1(804.53,630) 735,699.53 735,820 795,880 v1(795,1005) 780,1020 780,1175 665,1290
INTERRUPT: R26.2 R42.2 R79.1 R92.2 U13.2 | length 1406.5
  Top Layer w10: R92.2@528.53,833.44 615.09,920 815.29,920 855,959.71 855,1005 866.5,1016.5 866.5,1018.5 ; R42.2@741.5,1155 839,1155 ; v1(854,1208) 854,1170 839,1155 ; U13.2@1004.09,978.9 1004.09,1010.91 996.5,1018.5 R79.1@905,1018.5 866.5,1018.5 ; v1(1037,1304) 1138,1405 R26.2@1223.5,1405 ; 839,1155 855,1139 855,1030 866.5,1018.5
  Bottom Layer w10: v1(854,1208) 854,1269 889,1304 v1(1037,1304)
IR_ALERT: R78.1 R89.2 U13.1 | length 1357.1
  Top Layer w10: U13.1@978.5,978.9 R78.1@978.5,900 978.5,867.5 990,856 1079,856 1095,840 1305,840 1345,800 1345,789.21 ; R89.2@1018.03,554.5 1018.03,396.97 1040,375 1105,375 1170,440 1295,440 1333,478 1333,670 1345,682 1345,749.79 ; 1345.03,749.82 1345.03,789.18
